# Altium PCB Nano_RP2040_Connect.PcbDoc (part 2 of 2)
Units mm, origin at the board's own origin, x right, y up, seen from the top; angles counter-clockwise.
Board outline 43.18 x 17.78 mm, 4 copper layers (TOP, GND, SIG, BOTTOM), stack 1.586 mm thick; 92 components, 78 nets, 388 pads, 198 vias.
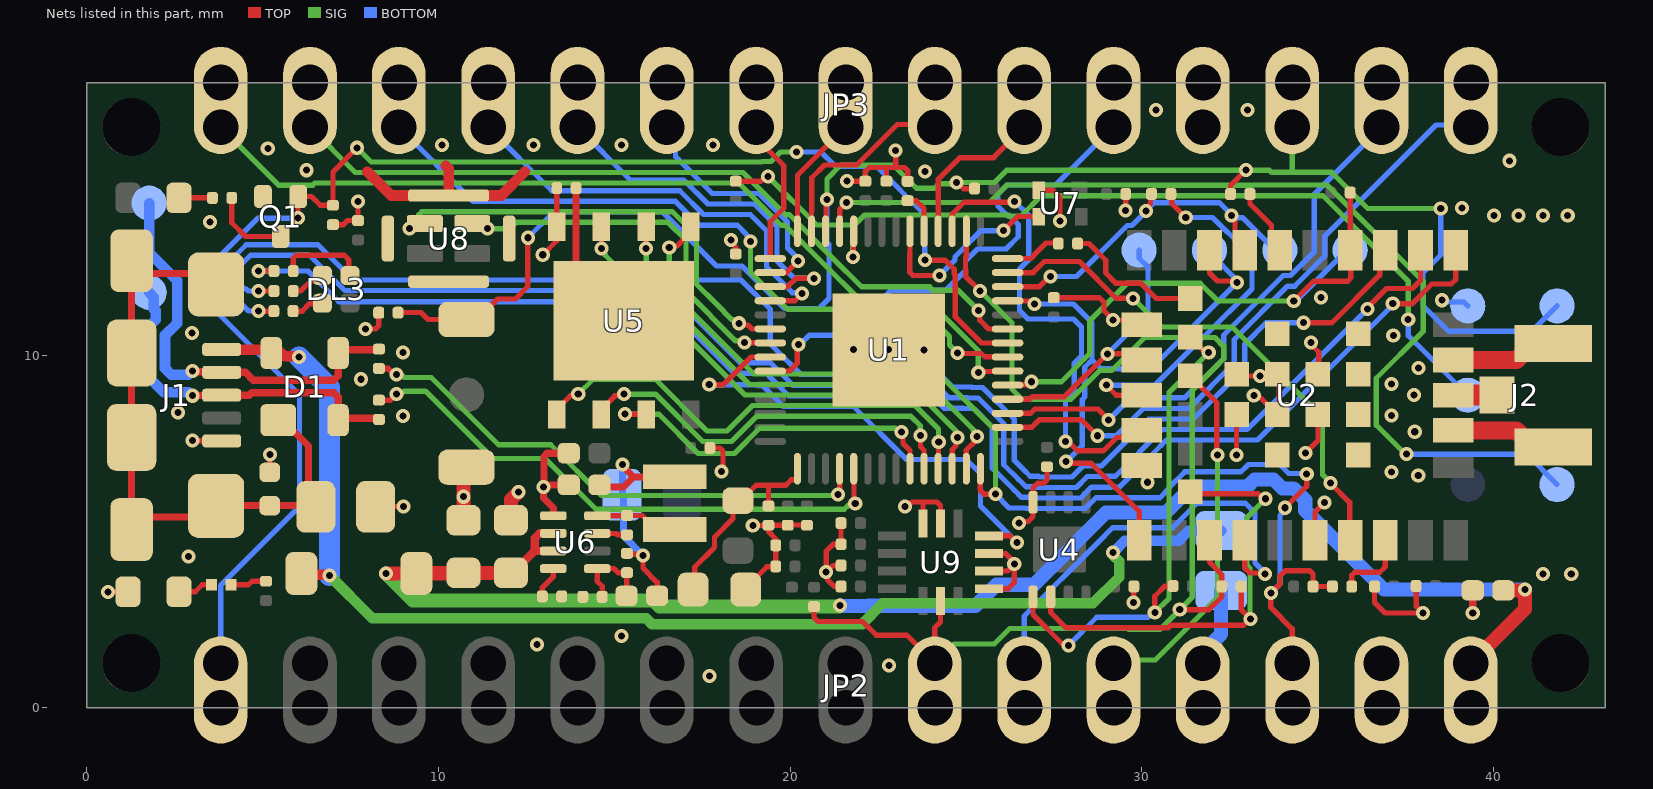
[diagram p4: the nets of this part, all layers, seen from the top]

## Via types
v1: diameter 0.4, hole 0.2, TOP to BOTTOM, tented both sides, 198 vias

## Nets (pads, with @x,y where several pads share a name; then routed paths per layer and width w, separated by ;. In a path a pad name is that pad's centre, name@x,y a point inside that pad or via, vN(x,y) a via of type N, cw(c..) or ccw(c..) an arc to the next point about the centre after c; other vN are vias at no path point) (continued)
A5/SCL~: JP2.9 R10.1 R17.1 U1.16 U2.3 U9.13 | length 37
  TOP w0.15: R10.1@20.676,2.871 20.676,2.563 20.792,2.447 22.055,2.447 22.446,2.055 23.315,2.055 JP2.9@24.109,1.261 24.109,2.271 24.269,2.431 U9.13@24.269,3.129 ; U1.16@25.004,13.541 25.004,12.817 24.981,12.794 24.981,12.442 24.987,12.436 24.987,12.257 v1(25.395,11.849) ; v1(31.074,2.784) 31.905,2.784 32.269,3.148 32.269,3.786 31.919,4.136 U2.3@31.919,4.756
  SIG w0.15: JP2.9@24.109,1.261 24.654,1.806 25.798,1.806 26.24,2.248 29.601,2.248 29.625,2.224 30.514,2.224 31.433,3.143 31.433,9.031 32.071,9.669 32.074,9.669 32.323,9.918 32.323,10.27 32.074,10.519 30.077,10.519 29.149,9.591 28.809,9.591 27.984,8.766 26.587,8.766 26.304,9.049 26.304,10.942 25.397,11.849 v1(25.395,11.849)
A6: JP2.10 U2.4 | length 12.6
  TOP w0.15: U2.4@32.919,4.756 32.919,3.973 33.068,3.824 33.46,3.824 v1(33.493,3.791)
  BOTTOM w0.15: JP2.10@26.649,1.261 26.649,2.596 28.733,4.68 29.169,5.116 30.874,5.116 31.57,5.812 32.934,5.812 33.212,5.534 33.212,4.112 33.493,3.831 v1(33.493,3.791)
A7: JP2.11 U2.34 | length 10.4
  TOP w0.15: U2.34@31.369,9.431 32.124,8.676 32.124,7.197 v1(32.142,7.18)
  SIG w0.15: JP2.11@29.189,1.261 29.281,1.353 30.376,1.353 32.144,3.121 32.144,7.177 v1(32.142,7.18)
ANT: J2.SIG U2.13 | length 1.3
  TOP w0.6: U2.13@38.844,8.881 J2.SIG@40.094,8.881
D2~: JP3.5 U1.37 | length 14.6
  TOP w0.15: U1.37@19.429,9.566 19.973,9.566 20.201,9.795 20.201,10.294 v1(20.234,10.326)
  BOTTOM w0.15: v1(20.234,10.326) 20.278,10.326 20.535,10.583 21.579,10.583 22.857,11.861 24.415,11.861 24.981,12.427 24.981,12.695 25.326,13.04 26.138,13.04 26.483,13.385 26.483,13.737 26.225,13.995 26.167,13.995 25.908,14.253 25.908,14.606 26.157,14.855 27.542,14.855 JP3.5@29.189,16.501
D3~: JP3.6 U1.18 | length 4.5
  TOP w0.15: U1.18@24.204,13.541 24.204,15.019 24.82,15.635 25.783,15.635 JP3.6@26.649,16.501
D4~: JP3.7 U1.27 | length 5.7
  TOP w0.15: U1.27@20.604,13.541 20.604,14.129 20.61,14.134 20.61,15.064 20.971,15.425 21.889,15.425 23.04,16.576 24.034,16.576 JP3.7@24.109,16.501
D5~: JP3.8 U1.28 | length 3.5
  TOP w0.15: U1.28@20.204,13.541 20.204,14.331 20.207,14.334 20.207,14.766 20.204,14.769 20.204,15.136 JP3.8@21.569,16.501
D6~: JP3.9 U1.29 | length 4.2
  TOP w0.15: JP3.9@19.029,16.501 19.029,16.193 19.813,15.409 19.813,14.195 19.429,13.812 U1.29@19.429,12.766
D7~: JP3.10 U1.30 | length 7.1
  TOP w0.15: U1.30@19.429,12.366 19.894,12.366 v1(20.224,12.696)
  BOTTOM w0.15: JP3.10@16.489,16.501 16.734,16.257 16.734,15.664 17.782,14.616 19.11,14.616 19.921,13.806 19.921,13.07 20.109,12.882 20.109,12.879 20.224,12.764 v1(20.224,12.696)
D8~: JP3.11 U1.31 | length 10.4
  TOP w0.15: U1.31@19.429,11.966 19.926,11.966 20.162,12.202 v1(20.679,12.202)
  BOTTOM w0.15: JP3.11@13.949,16.501 15.457,14.993 16.98,14.993 17.657,14.316 18.986,14.316 19.621,13.681 19.621,12.697 20.104,12.215 20.666,12.215 v1(20.679,12.202)
D9~: JP3.12 U1.32 | length 12.5
  TOP w0.15: U1.32@19.439,11.576 U1.32@19.429,11.566 20.127,11.566 v1(20.334,11.773)
  BOTTOM w0.15: JP3.12@11.409,16.501 13.217,14.693 16.856,14.693 17.533,14.016 18.862,14.016 19.321,13.557 19.321,12.532 20.059,11.794 20.312,11.794 v1(20.334,11.773)
D10~: JP3.13 U1.7 | length 20.7
  TOP w0.15: v1(24.754,10.086) 24.774,10.066 25.431,10.066 25.521,9.976 26.17,9.976 U1.7@26.179,9.966
  SIG w0.15: v1(18.87,13.253) 18.87,12.377 19.921,11.327 23.749,11.327 24.529,10.546 24.529,10.311 v1(24.754,10.086)
  BOTTOM w0.15: JP3.13@8.869,16.501 10.977,14.393 16.732,14.393 17.409,13.716 18.491,13.716 18.74,13.468 18.74,13.451 18.87,13.32 v1(18.87,13.253)
D_N: R4.2 U1.46 | length 15.3
  TOP w0.15: v1(21.357,6.063) 21.404,6.111 U1.46@21.404,6.791
  TOP w0.16: R4.2@8.304,9.641 8.564,9.641 8.739,9.466 v1(8.804,9.466)
  SIG w0.15: v1(8.804,9.466) 8.852,9.419 8.985,9.419 9.017,9.386 9.793,9.386 11.706,7.473 13.191,7.473 14.637,6.028 21.322,6.028 v1(21.357,6.063)
D_P: R5.2 U1.47 | length 16.1
  TOP w0.15: U1.47@21.804,6.791 21.814,6.782 21.814,5.831 v1(21.847,5.798)
  TOP w0.16: R5.2@8.304,8.741 8.629,8.741 v1(8.804,8.916)
  SIG w0.15: v1(8.804,8.916) 8.852,8.964 8.985,8.964 9.017,8.996 9.632,8.996 11.545,7.083 13.03,7.083 14.475,5.638 21.533,5.638 21.645,5.75 21.799,5.75 v1(21.847,5.798)
GND: C1.1 C2.2 C3.1 C4.1 C5.2 C6.2 C7.2 C8.2 C9.1 C10.2 C11.2 C12.2 C13.2 C14.2 C15.2 C16.2 C17.1 C18.2 C21.2 C22.1 C23.1 C24.2 C25.1 C26.2 C27.2 C28.2 C30.2 C32.2 C33.1 DL1.C J1.5 J2.GND JP2.14 JP3.4 PB1.1 Q1.S R1.1 R3.2 R8.1 R23.1 RPAD.2 TP_GND.X U1.57 U2.6 U2.12 U2.14 U2.26 U2.30 U2.GND1 U2.GND2 U2.GND3 U2.GND4 U2.GND5 U2.GND6 U2.GND7 U2.GND8 U2.GND9 U2.GND10 U2.GND11 U2.GND12 U4.4 U5.4 U6.1 U7.2 U8.5 U9.1 U9.2 U9.3 U9.6 U9.7 | length 60.6
  TOP w0.15: v1(0.604,3.291) DL1.C@1.169,3.291 ; v1(3.004,7.591) 3.009,7.586 3.829,7.586 J1.5@3.834,7.581 ; R1.1@5.201,6.689 5.203,6.691 5.203,7.19 v1(5.204,7.191) ; R23.1@6.996,13.731 7.299,13.731 7.414,13.846 C28.2@7.711,13.846 v1(7.711,14.392) ; v1(7.921,10.762) 8.202,10.762 8.298,10.857 C2.2@8.298,11.226 ; C1.1@8.21,5.706 8.22,5.716 v1(9.004,5.716) ; v1(12.962,12.875) 12.965,12.875 13.361,13.271 RPAD.2@13.361,14.771 ; C26.2@17.721,7.381 17.999,7.381 18.086,7.293 18.086,6.759 v1(18.04,6.712) ; v1(18.315,13.291) 18.315,13.224 18.45,13.088 C21.2@18.45,12.9 ; C9.1@18.735,3.355 18.735,3.405 19.33,4.001 19.574,4.001 C24.2@19.587,4.014 C33.1@19.587,4.614 19.587,4.795 19.38,5.002 C8.2@19.38,5.182 ; v1(18.934,5.173) 18.939,5.178 19.375,5.178 C8.2@19.38,5.182 ; C13.2@20.476,5.182 20.467,5.191 19.937,5.191 C18.2@19.928,5.182 19.923,5.187 19.384,5.187 C8.2@19.38,5.182 ; v1(21.015,3.851) 21.063,3.803 21.063,3.629 21.25,3.443 C32.2@21.445,3.443 ; C30.2@21.445,4.043 21.443,4.041 21.214,4.041 21.046,3.873 21.038,3.873 21.023,3.887 21.023,4.449 21.215,4.641 21.442,4.641 C6.2@21.445,4.643 ; C6.2@21.445,4.651 C5.2@21.445,5.243 ; v1(21.611,14.966) C10.2@22.134,14.966 22.134,15.246 22.246,15.358 22.748,15.358 ; C11.2@22.734,14.966 22.734,15.343 22.748,15.358 ; v1(22.994,15.843) 22.999,15.839 22.999,15.358 ; v1(23.267,5.719) 23.335,5.719 23.461,5.845 23.771,5.845 ; R3.2@23.338,14.962 23.338,15.27 23.25,15.358 22.999,15.358 ; U9.7@23.771,5.331 23.771,5.845 ; U9.6@24.271,5.331 24.271,5.74 24.166,5.845 23.771,5.845 ; U9.1@25.646,3.381 26.198,3.381 26.369,3.552 v1(26.369,4.079) ; U9.2@25.646,3.881 26.171,3.881 v1(26.369,4.079) ; U9.3@25.646,4.381 26.123,4.381 26.369,4.135 v1(26.369,4.079) ; v1(26.503,5.252) 26.543,5.291 26.766,5.291 26.904,5.429 U4.4@26.904,5.836 ; U4.4@26.869,5.916 26.904,5.952 26.904,6.25 27.036,6.381 27.211,6.381 27.299,6.469 C12.2@27.299,6.847 ; U7.2@27.067,14.708 27.467,14.708 27.672,14.503 v1(27.672,13.833) ; C7.2@27.491,11.654 28.305,11.654 28.786,11.654 28.917,11.523 28.917,11.281 v1(29.177,11.021) 29.855,11.021 U2.26@29.994,10.881 ; v1(29.536,14.129) 29.538,14.131 29.538,14.59 C14.2@29.539,14.591 ; v1(29.763,2.993) 29.766,2.996 29.766,3.439 C27.2@29.769,3.442 ; U2.30@29.994,6.881 30.151,6.724 v1(30.151,6.407) ; v1(32.692,7.18) 32.69,7.182 32.69,8.322 U2.GND11@32.699,8.332 ; U2.GND12@32.699,9.481 32.752,9.429 v1(33.357,9.429) ; v1(33.178,8.871) 33.226,8.824 33.357,8.824 U2.GND8@33.849,8.332 33.904,8.387 33.904,9.426 U2.GND9@33.849,9.481 ; v1(34.654,7.241) 35.004,7.591 35.004,8.327 U2.GND5@34.999,8.332 ; v1(34.81,10.386) 34.81,10.318 35.025,10.103 35.025,9.507 U2.GND6@34.999,9.481 ; U2.6@34.919,4.756 34.919,5.557 v1(35.193,5.83) ; C15.2@36.613,3.442 36.613,2.987 36.909,2.691 v1(37.984,2.691) 37.984,2.7 37.794,2.89 C16.2@37.794,3.453 ; 22.748,15.358 22.999,15.358
  TOP w0.2: v1@12.996,6.243 12.996,7.143 13.084,7.231 C17.1@13.701,7.231 ; U6.1@13.263,5.451 13.263,5.676 12.98,5.959 v1(12.98,6.266) 13.034,6.266 13.099,6.331 C3.1@13.701,6.331 ; v1(39.404,2.691) C25.1@39.404,3.291
  TOP w0.3: 7.978,15.231 8.65,14.559 U8.5@10.284,14.559 ; 10.2,15.4 10.284,15.316 U8.5@10.284,14.559 ; 12.45,15.231 11.778,14.559 U8.5@10.284,14.559
  TOP w0.4: C23.1@10.708,5.328 v1(10.708,5.995) 10.708,6.747 PB1.1@10.794,6.833 ; C4.1@12.058,5.328 12.058,5.918 v1(12.271,6.131)
  TOP w0.508: U2.12@38.844,7.881 40.644,7.881 41.119,7.406 J2.GND@41.694,7.406 ; U2.14@38.844,9.881 40.644,9.881 41.119,10.356 J2.GND@41.694,10.356
  BOTTOM w0.15: v1(38.526,11.581) 38.574,11.534 39.151,11.534 TP_GND.X@39.263,11.421
  other v1: 17.704,0.891 22.804,1.191 12.804,1.791 15.204,2.039 41.404,3.791 42.204,3.791 2.894,4.296 37.854,6.601 37.1,6.7 37.755,7.842 8.994,8.291 37.1,8.3 2.594,8.391 37.729,8.891 37.1,9.2 7.794,9.335 37.862,9.658 8.994,10.091 21.795,10.176 22.795,10.176 23.804,10.166 37.144,10.581 2.993,10.645 35.093,11.653 3.5,13.8 40.004,13.991 40.704,13.991 41.404,13.991 42.104,13.991 39.1,14.2 23.835,15.245 6.244,15.278 40.454,15.546 5.144,15.896 10.1,16 12.7,16 15.2,16 17.8,16 30.404,16.991 33.004,16.991
GPIO0: TP_GPIO0.X U1.4 U2.27 | length 8
  TOP w0.15: U1.4@26.179,8.766 26.814,8.766 26.887,8.839 27.795,8.839 v1(29.014,10.057) 29.819,10.057 U2.27@29.994,9.881
  BOTTOM w0.15: v1(29.014,10.057) 30.174,11.217 30.174,12.522 29.919,12.776 TP_GPIO0.X@29.919,13.006
INT1: U1.36 U9.4 | length 14.1
  TOP w0.15: v1(17.696,9.181) 18.101,9.181 18.887,9.966 U1.36@19.429,9.966 ; U9.4@25.646,4.881 26.244,4.881 26.433,4.693 v1(26.445,4.693)
  BOTTOM w0.15: v1(17.696,9.181) 19.185,9.181 19.8,8.567 21.789,8.567 23.301,7.056 25.004,7.056 25.409,6.651 25.409,5.729 v1(26.445,4.693)
LEDB: R13.2 U2.17 | length 42
  TOP w0.15: v1(4.878,11.841) R13.2@5.319,11.841 ; v1(36.411,11.332) 36.411,11.371 36.954,11.914 37.686,11.914 37.919,12.147 U2.17@37.919,13.006
  BOTTOM w0.15: v1(4.878,11.841) 4.591,11.841 4.533,11.9 4.482,11.9 4.346,12.036 4.346,12.551 4.655,12.859 6.329,12.859 7.331,11.857 16.523,11.857 18.573,9.807 19.43,9.807 20.071,9.167 24.14,9.167 24.494,8.812 25.033,8.812 25.045,8.8 25.345,8.8 26.071,8.074 26.071,6.904 26.496,6.479 ; 26.497,6.479 26.699,6.277 26.928,6.277 26.947,6.257 28.135,6.257 28.445,6.566 28.978,6.566 28.984,6.573 29.24,6.573 30.571,7.905 32.984,7.905 v1(36.411,11.332)
LEDG: R14.2 U2.16 | length 41.2
  TOP w0.15: v1(4.878,12.412) R14.2@5.319,12.412 ; v1(37.13,11.489) 37.14,11.479 37.675,11.479 38.238,12.041 38.794,12.041 38.919,12.166 U2.16@38.919,13.006
  BOTTOM w0.15: v1(4.878,12.412) 6.242,12.412 ; 6.292,12.412 7.164,11.54 16.365,11.54 18.399,9.507 19.306,9.507 19.947,8.867 24.015,8.867 24.37,8.512 24.909,8.512 24.921,8.5 25.22,8.5 25.736,7.985 25.736,6.816 25.771,6.781 ; 25.771,6.78 26.372,6.179 ; 26.373,6.179 26.575,5.977 26.804,5.977 26.823,5.957 28.26,5.957 28.569,6.266 29.102,6.266 29.109,6.273 29.364,6.273 30.548,7.457 30.696,7.605 33.285,7.605 37.13,11.449 v1(37.13,11.489)
LEDR: R15.2 U2.18 | length 42.8
  TOP w0.15: v1(4.874,11.271) R15.2@5.316,11.271 ; v1(34.594,10.942) 35.405,10.942 36.757,12.294 36.757,12.844 U2.18@36.919,13.006
  BOTTOM w0.15: v1(4.874,11.271) 4.869,11.277 4.599,11.277 4.019,11.857 4.019,12.647 4.531,13.159 6.572,13.159 7.574,12.157 18.603,12.157 19.429,11.33 19.429,10.337 19.63,10.137 20.3,9.467 24.264,9.467 24.619,9.112 25.157,9.112 25.169,9.1 25.469,9.1 26.371,8.198 26.371,7.028 26.62,6.779 ; 26.621,6.779 26.824,6.577 27.052,6.577 27.072,6.557 28.011,6.557 28.32,6.866 28.853,6.866 30.192,8.205 31.458,8.205 32.924,9.671 32.924,10.335 33.531,10.941 v1(34.594,10.942)
NetC1_2: C1.2 D1.1 J1.M1 J1.M2 J1.M3 J1.M4 J1.M5 J1.M6 R1.2 | length 18.9
  TOP w0.2: J1.M1@3.674,12.029 3.364,12.339 1.636,12.339 J1.M2@1.274,12.701 J1.M3@1.274,5.061 1.636,5.423 3.364,5.423 3.68,5.739 6.477,5.739 C1.2@6.51,5.706 6.305,5.912 6.305,7.439 5.492,8.251 D1.1@5.442,8.251
NetC3_2: C3.2 C20.2 L2.2 R6.2 SJ4.2 | length 7.4
  TOP w0.15: v1@15.227,6.877 v1(15.227,6.905) ; R6.2@15.358,4.384 15.386,4.356 15.782,4.356 v1(15.81,4.329) 15.81,3.965 16.215,3.561 C20.2@16.215,3.176
  TOP w0.2: C3.2@14.571,6.331 14.627,6.275 15.26,6.275 15.544,6.559 ; v1@15.227,6.877 15.544,6.559 ; L2.2@16.771,6.531 16.743,6.559 15.544,6.559
  BOTTOM w0.2: v1(15.227,6.905) 15.227,6.058 SJ4.2@15.221,6.052 15.255,6.019 15.255,4.884 v1(15.81,4.329)
NetC8_1: C8.1 C9.2 L1.1 U1.43 | length 5.9
  TOP w0.15: C9.2@17.235,3.355 17.283,3.403 17.283,3.994 17.843,4.555 17.843,4.844 18.371,5.371 18.371,5.713 18.551,5.894 18.603,5.894 19.03,6.32 19.39,6.32 ; C8.1@19.38,5.702 19.38,6.309 19.39,6.32 ; U1.43@20.204,6.791 20.204,6.499 20.181,6.476 20.029,6.476 19.874,6.32 19.39,6.32
NetC19_1: C19.1 L2.1 U6.8 | length 2.4
  TOP w0.15: U6.8@14.513,5.451 14.518,5.456 15.353,5.456 C19.1@15.358,5.461 15.791,5.461 16.221,5.031 L2.1@16.771,5.031
NetC19_2: C19.2 U6.7 | length 0.9
  TOP w0.15: U6.7@14.513,4.951 15.043,4.951 15.083,4.911 C19.2@15.358,4.911
NetC20_1: C20.1 R6.1 R8.2 U6.5 | length 2.4
  TOP w0.15: R8.2@14.652,3.149 14.652,3.45 14.513,3.59 U6.5@14.513,3.951 14.99,3.951 15.106,3.834 R6.1@15.358,3.834 15.351,3.828 15.351,3.183 C20.1@15.345,3.176
NetC22_2: C22.2 U6.4 | length 0.9
  TOP w0.15: C22.2@12.95,3.16 12.95,3.41 13.263,3.723 U6.4@13.263,3.951
NetDL1_A: DL1.A SJ2.1 | length 1
  TOP w0.15: DL1.A@2.619,3.291 3.081,3.291 3.281,3.491 SJ2.1@3.544,3.491
NetDL2_C: DL2.C R25.1 | length 0.9
  TOP w0.15: DL2.C@2.619,14.491 R25.1@3.569,14.491
NetDL3_2: DL3.2 R15.1 | length 0.8
  TOP w0.15: R15.1@5.916,11.271 6.123,11.271 6.336,11.484 6.632,11.484 DL3.2@6.644,11.496
NetDL3_3: DL3.3 R13.1 | length 1
  TOP w0.15: R13.1@5.919,11.841 6.077,11.841 6.367,12.132 6.54,12.132 DL3.3@6.694,12.286
NetDL3_4: DL3.4 R14.1 | length 2.5
  TOP w0.15: R14.1@5.869,12.412 5.866,12.415 5.866,12.771 5.954,12.859 7.327,12.859 7.444,12.741 DL3.4@7.444,12.296
NetJP2_12: JP2.12 SJ1.2 | length 2.3
  BOTTOM w0.4: JP2.12@31.729,1.261 31.729,1.566 32.252,2.089 SJ1.2@32.252,3.332
NetQ1_D: Q1.D R25.2 | length 2.3
  TOP w0.15: R25.2@4.119,14.491 4.119,13.783 4.511,13.391 Q1.D@5.508,13.391
NetR2_1: R2.1 SJ2.2 | length 1
  TOP w0.15: SJ2.2@4.144,3.491 4.599,3.491 4.702,3.594 5.091,3.594 R2.1@5.094,3.591
NetR3_1: R3.1 U1.19 | length 1.2
  TOP w0.15: R3.1@23.338,14.412 23.58,14.412 23.804,14.187 U1.19@23.804,13.541
NetR18_2: R18.2 U2.36 | length 4.1
  TOP w0.15: R18.2@28.169,13.191 28.494,13.191 28.969,12.717 28.969,12.357 29.265,12.061 29.975,12.061 30.404,11.632 U2.36@31.369,11.632
NetR20_1: R20.1 U2.8 | length 2.1
  TOP w0.15: R20.1@35.963,3.442 35.963,3.758 36.051,3.846 36.759,3.846 36.919,4.006 U2.8@36.919,4.756
NetR22_1: R22.1 U2.28 | length 10.7
  TOP w0.15: v1@28.964,9.145 v1(28.985,9.166) 29.269,8.881 U2.28@29.994,8.881 ; R22.1@30.821,14.587 R22.1@30.821,14.708 ; R22.1@30.821,14.59 R22.1@30.821,14.602 30.845,14.578 30.845,14.33 v1(31.244,13.931)
  BOTTOM w0.15: v1(28.985,9.166) 30.368,9.166 31.762,10.56 31.784,10.56 33.129,11.905 33.129,12.807 32.437,13.513 ccw(c31.919,13.006) 32.342,13.595 32.004,13.931 v1(31.244,13.931)
NetR28_1: R28.1 U2.21 | length 1.9
  TOP w0.15: R28.1@33.069,14.602 33.069,14.324 33.681,13.712 33.681,13.244 U2.21@33.919,13.006
NetRPAD_1: RPAD.1 U5.9 | length 4.3
  TOP w0.2: RPAD.1@13.911,14.771 13.911,12.356 U5.9@15.266,11.001
NetU1_20: U1.20 U7.3 | length 5.6
  TOP w0.15: U1.20@23.404,13.541 23.404,12.91 23.399,12.905 23.399,12.374 23.487,12.286 v1(24.239,12.286) ; v1(26.058,13.561) 26.459,13.962 27.063,13.962 U7.3@27.067,13.958
  BOTTOM w0.15: v1(24.239,12.286) 24.681,12.728 24.681,12.819 25.423,13.561 v1(26.058,13.561)
PDMCLK: U1.35 U8.3 | length 10.9
  TOP w0.15: U8.3@10.959,13.759 11.242,13.759 v1(11.387,13.615) ; v1(18.697,10.378) 18.702,10.372 19.423,10.372 U1.35@19.429,10.366
  SIG w0.15: v1(11.387,13.615) 12.024,13.615 12.205,13.796 16.526,13.796 17.034,13.288 17.034,11.839 18.447,10.426 18.649,10.426 v1(18.697,10.378)
PDMDIN: U1.34 U8.4 | length 13.2
  TOP w0.15: v1(9.177,13.616) 9.466,13.616 U8.4@9.609,13.759 ; v1(18.548,10.926) 18.596,10.878 18.798,10.878 18.909,10.766 U1.34@19.429,10.766
  SIG w0.15: v1(9.177,13.616) 9.437,13.876 9.437,14.008 9.525,14.096 16.65,14.096 17.334,13.412 17.334,12.035 17.883,11.485 18.345,11.024 18.382,11.024 18.48,10.926 v1(18.548,10.926)
QSPI_CSn: JP2.13 R19.1 R20.2 U1.56 U5.1 | length 34.2
  TOP w0.15: v1(16.559,13.077) 16.606,13.125 16.775,13.125 17.172,13.521 U5.1@17.171,13.671 ; U1.56@25.404,6.791 25.404,6.173 25.511,6.067 v1(25.834,6.067) ; v1(34.071,5.682) 34.684,6.294 v1(34.684,6.644) ; JP2.13@34.269,1.261 34.269,2.237 33.664,2.842 v1(33.664,3.254) 33.924,3.514 33.924,3.739 34.072,3.887 34.775,3.887 34.863,3.799 R19.1@34.863,3.442 R20.2@35.413,3.442
  SIG w0.15: v1(16.559,13.077) 16.559,11.89 18.963,9.486 24.222,9.486 25.736,7.972 25.834,7.875 v1(25.834,6.067)
  BOTTOM w0.15: v1(25.834,6.067) 26.224,5.677 26.679,5.677 26.699,5.657 28.384,5.657 28.693,5.966 30.509,5.966 30.758,6.215 30.758,6.244 31.217,6.704 32.816,6.704 33.025,6.912 33.916,6.912 34.171,6.657 34.671,6.657 v1(34.684,6.644) ; v1(33.664,3.254) 33.924,3.515 33.924,5.469 34.071,5.616 v1(34.071,5.682)
QSPI_SCK: U1.52 U5.6 | length 11.6
  TOP w0.15: U5.6@14.631,8.331 14.631,8.481 15.013,8.863 15.223,8.863 v1(15.271,8.911) ; v1(23.702,7.741) 23.702,7.418 23.804,7.316 U1.52@23.804,6.791
  SIG w0.15: v1(15.271,8.911) 16.167,8.911 17.513,7.565 18.327,7.565 19.042,8.28 23.43,8.28 23.694,8.016 23.694,7.749 v1(23.702,7.741)
QSPI_SD0: U1.53 U5.5 | length 13.7
  TOP w0.15: U5.5@13.361,8.331 13.362,8.481 13.743,8.863 13.924,8.863 v1(13.972,8.911) ; U1.53@24.204,6.791 24.213,6.8 24.213,7.547 v1(24.222,7.556)
  SIG w0.15: v1(13.972,8.911) 14.397,9.336 16.166,9.336 17.637,7.865 18.202,7.865 18.924,8.586 23.548,8.586 24.213,7.921 24.213,7.564 v1(24.222,7.556)
QSPI_SD1: U1.55 U5.2 | length 13.9
  TOP w0.15: v1(15.902,13.051) U5.2@15.901,13.671 ; U1.55@25.004,6.791 25.004,7.32 25.263,7.578 25.263,7.662 v1(25.311,7.71)
  SIG w0.15: v1(15.902,13.051) 15.902,12.123 18.839,9.186 23.921,9.186 25.203,7.904 25.203,7.885 25.311,7.778 v1(25.311,7.71)
QSPI_SD2: U1.54 U5.3 | length 14.1
  TOP w0.15: v1(14.632,13.051) U5.3@14.631,13.671 ; U1.54@24.604,6.791 24.604,7.337 24.704,7.437 24.704,7.444 24.711,7.45 24.711,7.627 v1(24.759,7.675)
  SIG w0.15: v1(14.632,13.051) 14.632,12.983 14.741,12.874 14.741,12.859 18.714,8.886 23.693,8.886 24.711,7.868 24.711,7.723 v1(24.759,7.675)
QSPI_SD3: U1.51 U5.7 | length 10.4
  TOP w0.15: v1(15.296,8.342) 15.884,8.342 U5.7@15.898,8.328 ; v1(23.16,7.833) 23.208,7.785 23.208,7.507 23.404,7.311 U1.51@23.404,6.791
  SIG w0.15: v1(15.296,8.342) 16.26,8.342 17.377,7.226 18.412,7.226 19.129,7.943 22.983,7.943 23.092,7.833 v1(23.16,7.833)
RESETN: C2.1 JP3.3 PB1.2 R12.1 R28.2 TP_RESETN.X U1.26 | length 48.8
  TOP w0.15: C2.1@8.836,11.234 9.504,11.234 9.705,11.033 PB1.2@10.794,11.033 11.094,11.033 11.676,11.615 12.183,11.615 12.537,11.969 v1(12.537,13.357) ; U1.26@21.004,13.541 21.014,13.551 21.014,14.409 v1(21.045,14.44) ; v1(24.722,14.93) 24.755,14.93 24.933,14.753 R12.1@25.297,14.753 ; R28.2@32.519,14.602 32.519,14.847 32.951,15.279 v1(32.961,15.279)
  SIG w0.15: v1(21.045,14.44) 21.045,15.031 21.432,15.418 22.94,15.418 23.592,14.766 24.092,14.766 24.222,14.896 24.687,14.896 v1(24.722,14.93) 25.809,14.93 26.158,15.279 33.618,15.279 33.681,15.216 34.269,15.216 ; JP3.3@34.269,16.501 34.269,15.216 ; v1(38.494,14.191) 36.42,14.191 35.395,15.216 34.269,15.216
  BOTTOM w0.15: v1(12.537,13.357) 13.273,14.093 16.363,14.093 17.902,12.554 18.629,12.554 19.836,11.348 20.817,11.348 21.104,11.635 21.104,13.17 21.045,13.229 v1(21.045,14.44) ; v1(38.494,14.191) 38.494,12.871 37.992,12.368 37.992,11.426 38.721,10.696 41.078,10.696 TP_RESETN.X@41.803,11.421
RSTN_NINA: R7.1 TP_RST.X U1.5 U2.19 | length 16.6
  TOP w0.15: U1.5@26.179,9.166 26.189,9.176 26.707,9.176 26.795,9.264 v1(26.862,9.264) ; v1(34.315,11.556) 34.881,12.123 35.847,12.123 35.935,12.211 U2.19@35.935,13.006 ; U2.19@35.919,13.006 R7.1@35.919,14.639
  SIG w0.15: v1(26.862,9.264) 27.708,9.264 28.518,10.074 28.518,11.006 29.573,12.061 31.658,12.061 32.162,11.556 v1(34.315,11.556)
  BOTTOM w0.15: v1(34.315,11.556) 34.383,11.556 35.833,13.006 TP_RST.X@35.919,13.006
RX: JP3.2 U1.3 | length 15.6
  TOP w0.15: U1.3@26.179,8.366 26.839,8.366 26.958,8.486 28.744,8.486 v1(29.049,8.181)
  BOTTOM w0.15: v1(29.049,8.181) 29.673,8.805 31.209,8.805 32.324,9.92 32.324,10.591 34.015,12.281 34.22,12.281 34.894,12.956 34.894,14.586 JP3.2@36.809,16.501
SCL_CRYPTO: R17.2 U2.31 U4.6 | length 13.3
  TOP w0.15: U4.6@27.404,3.146 27.404,2.703 27.842,2.265 30.747,2.265 30.818,2.336 32.879,2.336 33.066,2.524 33.066,2.538 32.819,2.785 R17.2@32.819,3.442 ; U2.31@31.369,6.131 31.421,6.08 33.301,6.08 33.444,5.937 v1(33.512,5.937)
  SIG w0.15: v1(33.08,2.524) 33.068,2.536 33.068,3.962 32.981,4.049 32.981,5.406 v1(33.512,5.937)
SDA_CRYPTO: R16.2 U2.35 U4.5 | length 14.6
  TOP w0.15: U4.5@26.904,3.146 26.904,2.644 27.733,1.816 27.867,1.816 v1(27.915,1.768) ; v1(30.364,2.698) 30.364,3.166 30.65,3.453 R16.2@30.88,3.453 ; U2.35@31.369,10.531 31.758,10.142 31.85,10.142 v1(31.898,10.094)
  SIG w0.15: v1(30.364,2.698) 30.765,3.099 30.765,8.962 v1(31.898,10.094)
  BOTTOM w0.15: v1(27.915,1.768) 28.714,2.568 30.166,2.568 30.296,2.698 v1(30.364,2.698)
SPI1_ACK/UART1_CTS: U1.13 U2.7 | length 14.7
  TOP w0.15: U1.13@26.179,12.366 26.906,12.366 27.221,12.681 28.221,12.681 29.266,11.636 v1(29.749,11.636) ; v1(35.354,6.385) 35.904,5.834 35.904,4.771 U2.7@35.919,4.756
  SIG w0.15: v1(29.749,11.636) 30.565,10.819 32.568,10.819 35.131,8.256 35.131,6.622 35.354,6.4 v1(35.354,6.385)
SPI1_CIPO/UART1_TX: TP_TX.X U1.11 U2.1 U2.23 | length 18.4
  TOP w0.15: U1.11@26.179,11.566 26.189,11.557 26.786,11.557 26.872,11.472 v1(26.939,11.472) ; v1(27.844,6.991) 27.892,6.944 28.557,6.944 29.919,5.581 U2.1@29.919,4.756 ; U2.23@31.919,13.006 31.919,12.357 32.147,12.129 32.656,12.129 v1(32.704,12.081)
  BOTTOM w0.15: v1(26.939,11.472) 28.054,11.472 28.577,10.948 28.577,9.879 28.373,9.675 28.373,8.83 28.305,8.762 28.305,7.447 27.849,6.991 v1(27.844,6.991) ; 28.594,9.875 28.838,9.632 30.255,9.632 v1(32.704,12.081) 32.704,12.149 31.919,12.934 TP_TX.X@31.919,13.006
SPI1_COPI/UART1_RTS: R18.1 U1.14 | length 1.6
  TOP w0.15: U1.14@26.179,12.766 26.843,12.766 26.931,12.854 26.931,12.864 27.275,13.208 27.603,13.208 R18.1@27.619,13.191
SPI1_CS/UART1_RX: R22.2 TP_RX.X U1.12 U2.22 | length 11
  TOP w0.15: U1.12@26.179,11.966 27.086,11.966 27.375,12.256 v1(27.397,12.256) ; v1(30.115,14.124) 30.115,14.191 30.241,14.318 30.241,14.586 R22.2@30.271,14.616 ; v1(32.542,13.996) 32.542,13.928 32.644,13.826 32.644,13.281 U2.22@32.919,13.006
  BOTTOM w0.15: v1(27.397,12.256) 28.133,12.256 29.582,13.704 29.712,13.704 30.115,14.107 v1(30.115,14.124) 30.347,14.356 32.196,14.356 32.542,14.01 v1(32.542,13.996) ; v1@32.554,14.003 v1@32.621,13.918 ; v1@32.673,13.929 32.861,13.929 33.783,13.006 TP_RX.X@33.919,13.006
SPI1_SCK: U1.17 U2.29 | length 13.7
  TOP w0.15: U1.17@24.604,13.541 24.604,14.03 24.941,14.367 26.35,14.367 v1(26.378,14.394) ; v1(27.827,7.57) 27.894,7.57 28.161,7.303 28.906,7.303 29.282,7.679 29.792,7.679 U2.29@29.994,7.881
  BOTTOM w0.15: v1(26.378,14.394) 26.783,13.989 26.783,12.738 26.514,12.469 26.514,11.296 26.763,11.047 28.054,11.047 28.277,10.824 28.277,10.003 28.073,9.799 28.073,8.954 27.827,8.709 v1(27.827,7.57)
SPICLK~: JP2.1 Q1.G R23.2 U1.8 | length 42.3
  TOP w0.15: v1(5.998,13.916) 6.003,13.92 6.003,14.527 Q1.G@6.008,14.531 6.39,14.531 6.64,14.281 R23.2@6.996,14.281 6.996,15.229 v1(7.684,15.916) ; v1(23.824,12.729) 23.831,12.722 24.404,12.722 24.664,12.462 24.664,12.335 24.687,12.312 24.687,11.115 25.436,10.366 U1.8@26.179,10.366
  SIG w0.15: v1(7.684,15.916) 8.085,15.514 19.183,15.514 19.196,15.528 19.451,15.528 19.721,15.797 v1(20.181,15.797)
  BOTTOM w0.15: JP2.1@3.804,1.261 3.804,3.471 6.049,5.716 6.049,8.895 3.719,11.226 3.719,12.771 4.863,13.916 v1(5.998,13.916) ; v1(20.181,15.797) 20.878,15.797 21.284,15.391 22.447,15.391 23.824,14.013 v1(23.824,12.729)
SPIRX~: JP3.15 U1.6 | length 25.7
  TOP w0.15: v1(25.345,9.525) 25.377,9.557 26.17,9.557 U1.6@26.179,9.566 U1.6@26.17,9.576
  SIG w0.15: JP3.15@3.804,16.501 5.453,14.853 6.42,14.853 6.482,14.914 18.535,14.914 19.736,13.713 19.852,13.713 21.478,12.087 21.481,12.087 21.907,11.661 23.839,11.661 25.345,10.154 v1(25.345,9.525)
SPITX~: JP3.14 U1.9 | length 22.4
  TOP w0.15: v1(25.355,11.29) 25.387,11.258 25.387,11.015 25.636,10.766 U1.9@26.179,10.766
  SIG w0.15: JP3.14@6.344,16.501 7.631,15.214 18.659,15.214 19.86,14.013 19.977,14.013 21.603,12.387 21.605,12.387 22.031,11.961 23.963,11.961 24.063,11.861 24.782,11.861 25.353,11.29 v1(25.355,11.29)
SWCLK: R11.1 TP_SWCLK.X U1.24 | length 26.7
  TOP w0.15: R11.1@18.45,14.966 19.168,14.966 19.304,15.103 v1(19.372,15.103) ; v1(21.779,12.812) 21.795,12.828 21.795,13.532 U1.24@21.804,13.541
  SIG w0.15: v1(19.372,15.103) 20.753,13.722 21.828,13.722 ; v1(21.779,12.812) 21.779,13.263 21.828,13.312 21.828,13.722 ; v1(37.569,11.032) 37.574,11.037 37.574,12.119 35.138,14.554 33.262,14.554 30.2,14.554 27.139,14.554 26.554,13.969 26.202,13.969 26.167,14.004 22.11,14.004 21.828,13.722
  BOTTOM w0.15: v1(37.569,11.032) 37.569,10.575 37.801,10.343 TP_SWCLK.X@39.263,8.881
SWDIO: TP_SWDIO.X U1.25 | length 29.1
  TOP w0.15: U1.25@21.404,13.541 21.404,14.161 v1(21.602,14.359)
  SIG w0.15: v1(21.602,14.359) 25.662,14.359 26.157,14.854 30.325,14.854 33.137,14.854 35.263,14.854 37.994,12.123 37.994,10.696 36.66,9.362 36.66,8.03 37.486,7.205 v1(37.523,7.205)
  BOTTOM w0.15: v1(37.523,7.205) 40.939,7.205 TP_SWDIO.X@41.803,6.341
TX: JP3.1 U1.2 | length 17.9
  TOP w0.15: U1.2@26.179,7.966 26.863,7.966 27.082,8.186 28.272,8.186 v1(28.73,7.728)
  BOTTOM w0.15: v1(28.73,7.728) 29.26,7.728 30.037,8.505 31.334,8.505 32.624,9.795 32.624,10.466 34.139,11.981 34.344,11.981 35.194,12.832 35.194,13.397 38.362,16.565 39.285,16.565 JP3.1@39.349,16.501
USB_N: D1.3 D-.X J1.2 R4.1 | length 12.2
  TOP w0.21: v1(3.004,9.566) 3.022,9.549 3.817,9.549 J1.2@3.834,9.531 4.509,9.531 4.731,9.31 5.515,9.31 7.019,9.31 7.142,9.433 D1.3@7.142,10.161 ; D1.3@7.172,10.191 7.187,10.176 8.289,10.176 R4.1@8.304,10.191
  BOTTOM w0.3: D-.X@1.772,14.342 1.772,12.934 2.572,12.134 2.572,10.932 2.221,10.581 2.221,9.642 2.397,9.466 2.877,9.466 2.977,9.566 v1(3.004,9.566)
USB_P: D1.2 D+.X J1.3 R5.1 | length 10
  TOP w0.21: v1(3.004,8.866) 3.012,8.874 J1.3@3.834,8.874 ; J1.3@3.834,8.881 4.622,8.881 4.69,8.95 5.365,8.95 7.019,8.95 7.142,8.827 D1.2@7.142,8.251 ; D1.2@7.202,8.191 7.232,8.221 8.274,8.221 R5.1@8.304,8.191
  BOTTOM w0.3: D+.X@1.772,11.802 1.906,11.669 1.906,11.332 1.962,11.277 1.962,11.028 1.721,10.788 1.721,9.435 2.19,8.966 2.877,8.966 2.977,8.866 v1(3.004,8.866)
VIN: C4.2 C23.2 C25.2 D2.C JP2.15 U6.2 U6.3 | length 45.1
  TOP w0.24: C4.2@12.058,3.828 12.108,3.828 12.731,4.451 ; U6.3@13.263,4.451 12.731,4.451 ; U6.2@13.263,4.951 12.872,4.951 12.731,4.811 12.731,4.451
  TOP w0.4: v1(8.509,3.811) D2.C@9.369,3.811 9.378,3.82 10.699,3.82 C23.2@10.708,3.828 C4.2@12.058,3.828 ; JP2.15@39.349,1.261 40.891,2.803 40.891,3.357 v1(40.889,3.36) 40.859,3.33 C25.2@40.274,3.33
  SIG w0.4: v1(8.509,3.811) 9.279,3.041 16.107,3.041 16.276,2.872 21.383,2.872 v1(21.411,2.9)
  BOTTOM w0.4: v1(21.411,2.9) 21.418,2.893 22.222,2.893 22.224,2.894 25.269,2.894 25.866,3.491 26.924,3.491 28.974,5.541 30.684,5.541 31.422,6.279 32.992,6.279 33.201,6.487 33.74,6.487 33.995,6.232 34.299,6.232 34.312,6.219 34.331,6.219 34.643,5.907 34.643,5.602 36.884,3.36 v1(40.889,3.36) v1(40.889,3.36)
VUSB: D1.4 D2.A J1.1 SJ1.1 | length 37.4
  TOP w0.3: J1.1@3.834,10.181 3.844,10.171 5.432,10.171 5.62,9.984 6.011,9.984 v1(6.03,9.964) ; D2.A@6.099,3.811 6.137,3.774 6.88,3.774 v1(6.899,3.755)
  SIG w0.3: v1(6.899,3.755) 8.115,2.539 15.903,2.539 16.069,2.372 22.041,2.372 22.632,2.963 28.602,2.963 29.349,3.71 29.349,4.158 29.196,4.31 29.196,4.386 v1(29.177,4.405)
  BOTTOM w0.3: v1(29.177,4.405) 29.513,4.741 31.038,4.741 31.329,5.032 SJ1.1@32.252,5.032
  BOTTOM w0.6: v1(6.03,9.964) 6.899,9.096 v1(6.899,3.755)
pads on no net: Fiducial_2.1 J1.4 JP2.3 U1.21 U2.5 U2.11 U2.15 U2.20 U2.24 U2.25 U2.32 U2.33 U4.1 U4.2 U4.3 U4.7 U4.9 U6.6 U9.9 U9.10 U9.11

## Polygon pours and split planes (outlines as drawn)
no net on Top Overlay "GND_SILK" (solid): 30.444,17.771 30.444,14.871 32.944,14.871 32.944,17.771 32.541,17.771 32.541,16.471 cw(c31.752,16.479) 31.745,15.69 cw(c31.722,16.494) 30.917,16.471 30.917,17.771
no net on Top Overlay "GND_SILK" (solid): 38.094,-0.009 38.094,2.891 35.594,2.891 35.594,-0.009 35.997,-0.009 35.997,1.291 cw(c36.787,1.284) 36.794,2.073 cw(c36.817,1.269) 37.621,1.291 37.621,-0.009
GND on TOP "GND_TOP" (solid, remove dead copper, pour order 1): -0.006,-0.009 -0.006,17.771 43.174,17.771 43.174,-0.009
GND on GND "GND_2" (solid, remove dead copper, pour order 0): -0.006,17.771 -0.006,-0.009 43.174,-0.009 43.174,17.771
GND on BOTTOM "GND_BOT" (solid, remove dead copper, pour order 4): -0.006,-0.009 -0.006,17.771 43.174,17.771 43.174,-0.009
+3V3 on SIG "PWR" (solid, remove dead copper, pour order 3): -0.006,-0.009 -0.006,17.771 43.174,17.771 43.174,-0.009

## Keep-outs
SIG:
  region: 9.804,9.866 8.404,9.866 8.404,8.5 9.501,8.5 11.27,6.73 12.782,6.73 14.171,5.342 22.22,5.342 22.22,6.39 21.219,6.39 14.816,6.39 13.429,7.828 11.843,7.828

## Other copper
TOP:
  pour cut-out: 12.537,15 12.537,11.9 8.1,11.9 8.1,15
  pour cut-out: 43.156,4.129 39.346,4.129 39.346,13.624 43.156,13.624
GND:
  pour cut-out: 43.156,4.129 39.346,4.129 39.346,13.624 43.156,13.624
SIG:
  pour cut-out: 43.156,4.129 39.346,4.129 39.346,13.624 43.156,13.624
BOTTOM:
  pour cut-out: 15.015,6.865 14.9,6.75 14.9,5.255 17.105,5.255 17.2,5.35 17.2,6.865
  pour cut-out: 32.254,4.826 31.384,4.826 31.384,3.332 32.252,3.332
  pour cut-out: 40.094,15.891 40.894,15.891 40.894,17.491 40.094,17.491
  pour cut-out: 43.156,4.129 39.346,4.129 39.346,13.624 43.156,13.624
  text "..." at 40.694,16.091 h0.4 r90

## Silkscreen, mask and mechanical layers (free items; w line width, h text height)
Top Overlay:
  drawing of 14 lines, arcs and shapes, not listed
  text "." at 28.64,15.187 h0.1 r90
  text "." at 17.882,14.43 h0.1 r90
  text "." at 8.105,11.725 h0.1 r90
  text "." at 26.468,6.424 h0.1 r90
  text "." at 28.81,6.216 h0.1 r90
  text "." at 12.89,5.937 h0.1 r90
  text "." at 26.267,2.881 h0.1 r90
Bottom Overlay:
  drawing of 235 lines, arcs and shapes, not listed
Top 3D Body:
  the board outline again, w0.01
Route Tool Path:
  lines w2: -1.006,0.991 -1.006,-0.009 ccw(c-0.006,-0.009) -0.006,-1.009 43.174,-1.009 ccw(c43.174,-0.009) 44.174,-0.009 44.174,6.491 ; -1.006,4.991 -1.006,12.991 ; -1.006,16.991 -1.006,17.771 cw(c-0.006,17.771) -0.006,18.771 43.174,18.771 cw(c43.174,17.771) 44.174,17.771 44.174,10.491
Board:
  the board outline again, w0.1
